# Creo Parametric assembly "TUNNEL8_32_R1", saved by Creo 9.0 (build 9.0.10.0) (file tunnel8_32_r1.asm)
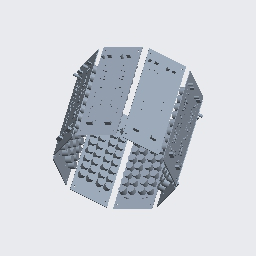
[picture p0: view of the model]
Units: millimeter Newton Second (mmNs); MM, TONNE, SECS

Created from: XX_MMNS_ASM_DESIGN_ABS.ASM

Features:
  1. datum plane "ASM_RIGHT"
  2. datum plane "ASM_TOP"
  3. datum plane "ASM_FRONT"
  4. coordinate system
  5. coordinate system
  6. component "PANEL32_R1"
  7. coordinate system
  8. component "PANEL32_R1"
  9. coordinate system
  10. component "PANEL32_R1"
  11. coordinate system
  12. component "PANEL32_R1"
  13. coordinate system
  14. component "PANEL32_R1"
  15. coordinate system
  16. component "PANEL32_R1"
  17. coordinate system
  18. component "PANEL32_R1"
  19. coordinate system
  20. component "PANEL32_R1"

Other named items: ACS0, ACS1, ACS2, ACS3, ACS4, ACS5, ACS6, ACS7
